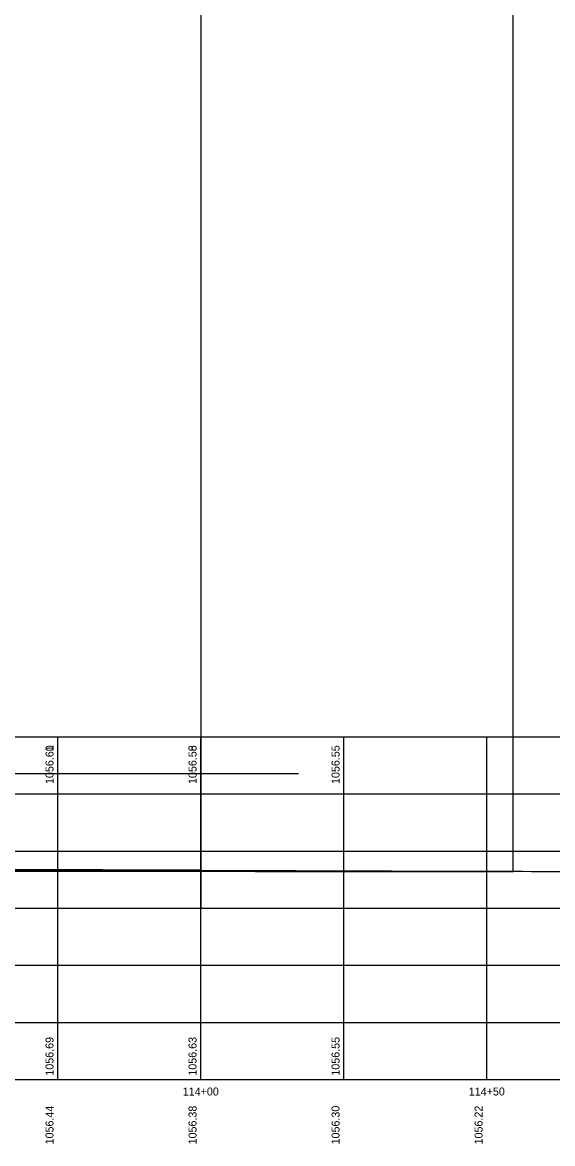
# Model space of a CAD drawing. Extents: x -1300 to 1299, y -770 to 1120.
# Drawn here: x 762.1 to 854.8, y -417.1 to -221 of the extents above; entities that cross this region are included whole.
import ezdxf

# ---------------------------------------------------------------- set-up
doc = ezdxf.new("R2010")
doc.units = 0
for name, color, linetype in [('PF_X_Ground_Line', 7, 'Continuous'), ('SC_Scratch1', 7, 'Continuous'), ('SC_Scratch2', 7, 'Continuous'), ('SC_Scratch3', 7, 'Continuous'), ('XS_P_Pavt_Surface', 7, 'Continuous')]:
    doc.layers.add(name, color=color, linetype=linetype)

msp = doc.modelspace()

# ---------------------------------------------------------------- linework, layer by layer
at = {"layer": 'PF_X_Ground_Line'}
msp.add_line((793.26, -369.3), (843.26, -369.46), dxfattribs=at)
for centre, radius, start, end in [((630.76, -62869.54), 62500.46, 89.8510313, 89.8968677), ((1080.77, 62131.18), 62501.09, 269.7822771, 269.8281131)]:
    msp.add_arc(centre, radius, start, end, dxfattribs=at)
at = {"layer": 'SC_Scratch1'}
for p, q in [((847.88, -369.47), (847.88, 439.29)), ((293.26, -345.93), (1018.26, -345.93)), ((768.26, -405.93), (768.26, -345.93)), ((793.26, -405.93), (793.26, -345.93)), ((818.26, -405.93), (818.26, -345.93)), ((843.26, -405.93), (843.26, -345.93)), ((293.26, -355.93), (1018.26, -355.93)), ((293.26, -365.93), (1018.26, -365.93)), ((293.26, -375.93), (1018.26, -375.93)), ((293.26, -385.93), (1018.26, -385.93)), ((293.26, -395.93), (1018.26, -395.93)), ((293.26, -405.93), (1018.26, -405.93))]:
    msp.add_line(p, q, dxfattribs=at)
at = {"layer": 'SC_Scratch2'}
msp.add_line((793.26, 424.91), (793.26, -375.93), dxfattribs=at)
at = {"layer": 'SC_Scratch3'}
msp.add_line((710.38, -352.36), (810.38, -352.36), dxfattribs=at)
at = {"layer": 'XS_P_Pavt_Surface'}
for p, q in [((710.38, -369.26), (847.88, -369.47)), ((710.38, -369.38), (847.88, -369.6)), ((847.88, -369.6), (847.88, -369.47))]:
    msp.add_line(p, q, dxfattribs=at)

# ---------------------------------------------------------------- texts
at = {"layer": 'SC_Scratch1'}
for s, p in [('1056.60', (767.53, -354.2)), ('1056.61', (767.53, -354.2)), ('1056.55', (792.53, -354.2)), ('1056.58', (792.53, -354.2)), ('1056.55', (817.53, -354.2)), ('1056.69', (767.53, -405.23)), ('1056.63', (792.53, -405.23)), ('1056.55', (817.53, -405.23)), ('1056.44', (767.53, -417.26)), ('1056.38', (792.53, -417.26)), ('1056.30', (817.53, -417.26)), ('1056.22', (842.53, -417.26))]:
    msp.add_text(s, height=1.4, rotation=90, dxfattribs=at).set_placement(p)
for s, p in [('114+00', (790.12, -408.71)), ('114+50', (840.12, -408.71))]:
    msp.add_text(s, height=1.4, dxfattribs=at).set_placement(p)

doc.saveas('drawing.dxf')
